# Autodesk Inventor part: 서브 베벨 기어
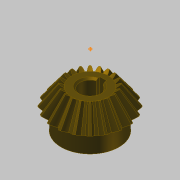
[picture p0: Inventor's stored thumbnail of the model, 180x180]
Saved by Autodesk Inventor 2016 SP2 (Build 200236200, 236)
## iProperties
Created: 2016-04
Part Number: 서브 베벨 기어
Material: 강철, 탄소
Document SubType Name: Modeling
Designer: mdu
Categories: <?xml version="1.0" encoding="UTF-16"?> <MemberInstance><Categories><FamilyTemplate><FamilyTemplateParameter ValueType="xs:double" Id="1" ObjectReferenceKey="da
Mass: 135.037 g
Surface Area: 63.6518 cm^2
Volume: 17.1585 cm^3
Density: 7.87 g/cm^3
Appearance: 얼룩무늬
CustomPartVersion: 1
Author: mdu
Revision Number: 1
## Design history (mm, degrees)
node "맨 위 점"
node "메쉬 평면2"
sketch "톱니 본체 스케치"
  geometry: L1 (0, 0)-(18.003, -31.331); L2 (18.003, -31.331)-(21.664, -28.891); L3 (21.664, -28.891)-(0, 0); L4 (20, -30)-(0, 0); L5 (10.813, -18.818)-(13.012, -17.352); L6 (18.003, -31.331)-(10.813, -18.818); L7 (21.664, -28.891)-(13.012, -17.352); L8 (0, -39.387)-(0, 6.564) reference; L9 (0, -30)-(21.664, -30)
  constraints: 16 end point, 4 point on line, 3 perpendicular, 2 collinear, 1 horizontal alignment, 1 vertical alignment
  dimensions: "d0" = 40 diameter of L4.start L8 (= da_de); "d1" = 36.00616 diameter of L1.end L8 (= da_dfe); "d2" = 43.3282 diameter of L2.end L8 (= da_dae); "d3" = 14.4 distance between parallel lines of L2 L5 (= da_b); "d4" = 28.8906 vertical distance of L2.end L1.start (= da_ve)
revolve "톱니 본체" sketch "톱니 본체 스케치" stored, may be unused: angle "d5" = 90 deg
node "시작점"
node "톱니 평면"
sketch "시작 스케치"
  geometry: L1 (0, -23.505)-(0, 10.645) reference; L2 (-0.834, -2.928)-(0.834, -2.928); A1 r 8.898 centre (-9.698, -3.713) between (-0.834, -2.928) and (-3.903, 3.04); A2 r 8.898 centre (9.698, -3.713) between (3.903, 3.04) and (0.834, -2.928); A3 r 27.357 centre (0, -24.037) between (3.903, 3.04) and (-3.903, 3.04); 1 further point
  constraints: 6 point on circle, 3 centre point, 3 symmetric about line, 2 end point, 1 coincident, 1 perpendicular, 1 other
  dimensions: "d7" = 8.89846 radius of A1 (= fd_rr); "d8" = 9.69794 horizontal distance of point (0, -24.037) A1.centre (= fd_x); "d9" = 20.32439 vertical distance of point (0, -24.037) A1.centre (= fd_y); "d57" = 27.35701 radius of A3 (= 0.5 x fd_dva + 0.3 x da_he); "d58" = 21.10901 distance from line of A3.centre L2 (= 0.5 x fd_dva - 1.12 x da_he)
node "끝점"
  node "끝 평면"
sketch "3D 스케치 오른쪽"
  node "Helical Curve Right" dims "d65" = 229.90621 (computed from da_dm, da_delta, da_beta), "d66" = 31.5, "d67" = 40 (= da_de), "d68" = -5.88003 (= -da_delta), "d69" = 12.16458 (computed from fd_loft, da_delta)
node "끝 평면 오른쪽"
sketch "끝 스케치 오른쪽"
  geometry: L1 (0, -22.649)-(0, 12.15) reference; L2 (-0.497, -1.72)-(0.497, -1.72); A1 r 5.299 centre (-5.775, -2.187) between (-0.497, -1.72) and (-2.324, 1.834); A2 r 5.299 centre (5.775, -2.187) between (2.324, 1.834) and (0.497, -1.72); A3 r 16.291 centre (0, -14.29) between (2.324, 1.834) and (-2.324, 1.834); 1 further point
  constraints: 6 point on circle, 3 centre point, 3 symmetric about line, 2 end point, 1 coincident, 1 perpendicular, 1 other
  dimensions: "d70" = 5.77526 horizontal distance of A3.centre A1.centre (computed from fd_x, fd_ratio); "d71" = 12.10346 vertical distance of point (0, -14.29) A1.centre (computed from fd_y, fd_ratio); "d72" = 5.29916 radius of A1 (computed from fd_rr, fd_ratio); "d73" = 12.57071 distance from line of point (0, -14.29) L2 (computed from d58, fd_ratio); "d74" = 16.29149 radius of A3 (computed from d57, fd_ratio)
feature "로프트 오른쪽" sketch "끝 스케치 오른쪽" dims "d75" = 0, "d77" = 0, "d79" = 0, "d80" = 90 deg, "d85" = 20, "d92" = 90 deg, "d93" = 90 deg, "da_teethtype" = 0 [user parameter]
sketch "3D 스케치 왼쪽"
  node "Helical Curve Left" dims "d26" = 229.90621 (computed from da_dm, da_delta, da_beta), "d27" = 12.16458 (computed from fd_loft, da_delta), "d28" = 40 (= da_de), "d29" = -5.88003 (= -da_delta)
node "끝 평면 왼쪽"
sketch "끝 스케치 왼쪽" dims "d56" = 10.82768 (derived)
  geometry: L1 (0, -35.087)-(0, 18.089) reference; L2 (-0.497, -1.716)-(0.497, -1.716); A1 r 5.299 centre (-5.775, -2.183) between (-0.497, -1.716) and (-2.324, 1.838); A2 r 5.299 centre (5.775, -2.183) between (2.324, 1.838) and (0.497, -1.716); A3 r 16.291 centre (0, -14.287) between (2.324, 1.838) and (-2.324, 1.838); 2 further points; 1 other entity
  constraints: 6 point on circle, 3 centre point, 3 symmetric about line, 2 end point, 1 coincident, 2 other
  dimensions: "d30" = 5.29916 radius of A1 (computed from fd_rr, fd_ratio); "d31" = 5.77526 horizontal distance of point (0, -14.287) A1.centre (computed from fd_x, fd_ratio); "d32" = 12.10346 vertical distance of A1.centre point (0, -14.287) (computed from fd_y, fd_ratio); "d61" = 16.29149 radius of A3 (computed from d57, fd_ratio); "d62" = 12.57071 distance from line of point (0, -14.287) L2 (computed from d58, fd_ratio)
feature "로프트 왼쪽" sketch "끝 스케치 왼쪽" dims "d35" = 0, "d37" = 0, "d39" = 0, "d40" = 90 deg, "d84" = 10, "d90" = 90 deg, "d91" = 90 deg, "da_teethtype" = 0 [user parameter]
sketch "본체 스케치"
  geometry: L1 (0, -35.038)-(0, -19.531) reference; L2 (18.003, -31.331)-(10.813, -18.818) reference; L3 (10.813, -18.818)-(0, -18.818); L4 (18.003, -31.331)-(0, -31.331)
  constraints: 4 end point, 2 perpendicular, 2 point on line
revolve "본체 고정" sketch "본체 스케치" stored, may be unused: angle "d46" = 90 deg
feature "피치 지름" dims angle "d47" = 90 deg
sketch "스케치8"
  geometry: C1 r 17 at (0, 0); 1 further point
  constraints: 1 centre point, 1 coincident
  dimensions: "d94" = 34 diameter of C1
extrude "돌출1" join sketch "스케치8" distance "d95" = 10; taper "d96" = 0 deg
sketch "스케치9"
  geometry: 1 further point
hole "구멍1" sketch "스케치9" at (0, 0) diameter "d97" = 12; stored, may be unused: countersink angle "d101" = 90 deg, drill point angle "d103" = 118 deg; dims "d98" = 6, "d99" = 4, "d100" = 2, "d102" = 8
sketch "스케치10"
  geometry: 1 further point
sketch "스케치11"
  geometry: 1 further point
sketch "스케치12"
  geometry: L1 (-2, 5.657)-(-2, 7.8); L2 (-2, 7.8)-(2, 7.8); L3 (2, 7.8)-(2, 5.657); A1 r 6 centre (0, 0) between (-2, 5.657) and (2, 5.657) reference; 1 further point
  constraints: 6 end point, 2 parallel, 2 point on circle, 1 perpendicular, 1 vertical
  dimensions: "d104" = 4 distance of L1.end L2.end; "d105" = 13.8 dimension on A1 L2
extrude "돌출2" cut sketch "스케치12" stored distance "d106" = 7; taper "d107" = 0 deg
chamfer "모따기1" distance "d108" = 1; stored, may be unused: second distance "d109" = 2, angle "d110" = 45 deg
body "Solid1"
feature "로프트" dims "d17" = 0, "d18" = 90 deg, "d19" = 0, "d20" = 90 deg, "d89" = 0, "da_teethtype" = 0 [user parameter]
pattern_circular "원형 패턴" dims angle "d22" = 360 deg, "d88" = 0, "da_teethtype" = 0 [user parameter]
pattern_circular "원형 패턴 오른쪽" dims angle "d82" = 360 deg, "da_teethtype" = 0 [user parameter]
pattern_circular "원형 패턴 왼쪽" dims angle "d42" = 360 deg, "da_teethtype" = 0 [user parameter]
sketch "끝 스케치"
  geometry: L1 (0, -15.359)-(0, 6.983) reference; L2 (-0.497, -1.72)-(0.497, -1.72); A1 r 5.299 centre (-5.775, -2.187) between (-0.497, -1.72) and (-2.324, 1.834); A2 r 5.299 centre (5.775, -2.187) between (2.324, 1.834) and (0.497, -1.72); A3 r 16.291 centre (0, -14.29) between (2.324, 1.834) and (-2.324, 1.834); 1 further point
  constraints: 6 point on circle, 3 centre point, 3 symmetric about line, 2 end point, 1 coincident, 1 other
  dimensions: "d12" = 5.29916 radius of A1 (computed from fd_rr, fd_ratio); "d15" = 5.77526 horizontal distance of A1.centre point (0, -14.29) (computed from fd_x, fd_ratio); "d16" = 12.10346 vertical distance of A1.centre point (0, -14.29) (computed from fd_y, fd_ratio); "d59" = 16.29149 radius of A3 (computed from d57, fd_ratio); "d60" = 12.57071 distance from line of A3.centre L2 (computed from d58, fd_ratio)
sketch "Sketch6"
  geometry: L1 (20, -30)-(0, 0) reference; L2 (0, -37.8)-(0, 6.3) reference
body "Srf1"
other parameters: "da_b" = 14.4 [user parameter; used in 2 equation terms], "da_de" = 40 [user parameter; used in 4 equation terms], "da_dae" = 43.3282 [user parameter; used in 2 equation terms], "da_dfe" = 36.00616 [user parameter; used in 1 equation term], "da_le" = 36.05551 [user parameter; used in 1 equation term], "da_omega" = 90 deg [user parameter; used in 1 equation term], "da_beta" = 0 [user parameter; used in 2 equation terms], "da_delta" = 5.88003 [user parameter; used in 8 equation terms], "da_alpha" = 20 deg [user parameter; used in 2 equation terms], "da_he" = 4.4 [user parameter; used in 4 equation terms], "da_ve" = 28.8906 [user parameter; used in 1 equation term], "fd_dv" = 48.07402 (computed from da_de, da_delta) [user parameter; used in 1 equation term], "fd_dva" = 52.07402 (computed from da_dae, da_delta) [user parameter; used in 3 equation terms], "fd_dvb" = 45.1748 (computed from fd_dv, da_alpha) [user parameter; used in 2 equation terms], "da_zv" = 240.37008 [user parameter; used in 1 equation term], "fd_loft" = 14.62 (= da_b + 0.05 x da_he) [user parameter; used in 4 equation terms], "fd_ratio" = 5.95514 (computed from da_le, fd_loft) [user parameter; used in 15 equation terms], "fd_rr" = 8.89846 (computed from fd_dd, fd_dvb) [user parameter; used in 6 equation terms], "fd_angle" = 0.66075 (computed from da_zv) [user parameter; used in 4 equation terms], "fd_x1" = 1.58709 (computed from da_dvw, fd_angle) [user parameter; used in 1 equation term], "fd_y1" = 23.98456 (computed from da_dvw, fd_angle) [user parameter; used in 1 equation term], "fd_x2" = 8.11084 (computed from fd_rr, fd_angle2, fd_angle) [user parameter; used in 1 equation term], "fd_y2" = 3.66016 (computed from fd_rr, fd_angle2, fd_angle) [user parameter; used in 1 equation term], "fd_x" = 9.69794 (= fd_x1 + fd_x2) [user parameter; used in 4 equation terms], "fd_y" = 20.32439 (= fd_y1 - fd_y2) [user parameter; used in 4 equation terms], "fd_angle2" = 3.57832 (computed from fd_dvb, fd_dd, da_alpha) [user parameter; used in 2 equation terms], "fd_dd" = 48.55402 (= fd_dva - 0.8 x da_he) [user parameter; used in 2 equation terms], "da_dvw" = 48.07402 [user parameter; used in 2 equation terms], "d11" = 14.62 (= fd_loft), "da_dm" = 32.01232 [user parameter; used in 2 equation terms], "da_x" = 0 [user parameter], "da_m" = 2 [user parameter], "d48" = 0, "d49" = 0, "d50" = 90 deg (= da_omega), "d51" = 9 deg (computed from da_z), "d52" = 0, "d53" = 0, "d54" = 0
